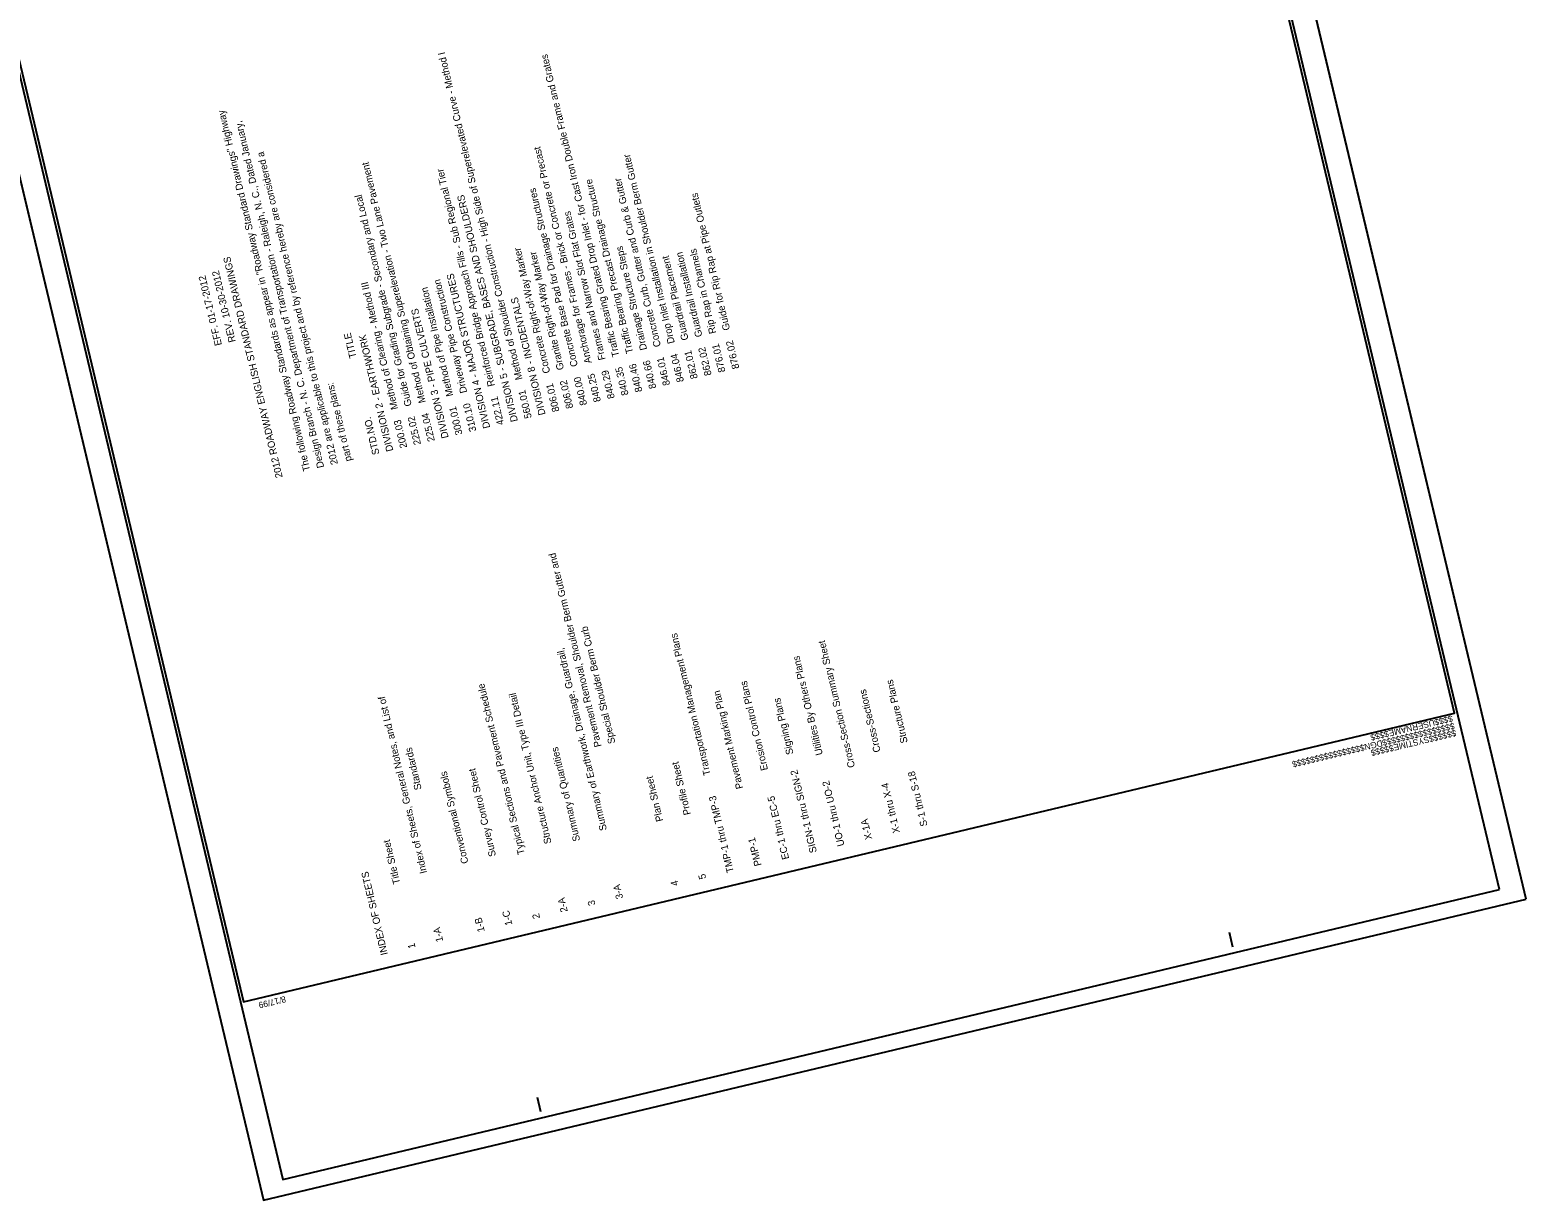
# Model space of a CAD drawing. Extents: x 1734738 to 1742883, y 698103 to 703125.
# Drawn here: x 1740359 to 1742883, y 699342 to 701316 of the extents above; entities that cross this region are included whole.
import ezdxf

# ---------------------------------------------------------------- set-up
doc = ezdxf.new("R2010")
doc.units = 0
for name, color, linetype in [('Default', 7, 'Continuous'), ('Exist Road Primary US Structure Standard Bridge Number Label', 7, 'Continuous'), ('Exist Road Secondary Structure Pipe Number Label', 7, 'Continuous'), ('Exist Road Secondary Type 41 SR Number Label', 7, 'Continuous'), ('Exist Road Secondary Type 51 Number Label', 7, 'Continuous'), ('Map Preparation County Base Positioning Point', 7, 'Continuous')]:
    doc.layers.add(name, color=color, linetype=linetype)

msp = doc.modelspace()

# ---------------------------------------------------------------- linework, layer by layer
at = {"layer": 'Exist Road Primary US Structure Standard Bridge Number Label'}
for p, q in [((1742882.7, 699849.5), (1742102.1, 703124.7)), ((1739971.8, 702617), (1740752.4, 699341.7)), ((1740752.4, 699341.7), (1742882.7, 699849.5))]:
    msp.add_line(p, q, dxfattribs=at)
at = {"layer": 'Exist Road Secondary Structure Pipe Number Label'}
msp.add_lwpolyline([(1742837.8, 699865.5), (1742065.3, 703106.7), (1740012.8, 702617.5), (1740785.3, 699376.3)], close=True, dxfattribs=at)
at = {"layer": 'Exist Road Secondary Type 41 SR Number Label'}
msp.add_lwpolyline([(1742882.7, 699849.5), (1742102.1, 703124.7), (1739971.8, 702617), (1740752.4, 699341.7)], close=True, dxfattribs=at)
at = {"layer": 'Map Preparation County Base Positioning Point'}
for p, q in [((1742761.7, 700163), (1742761.7, 700163)), ((1742388, 699768.6), (1742382.2, 699792.9)), ((1740719, 699676.1), (1740719, 699676.1)), ((1741220.7, 699490.4), (1741214.9, 699514.7))]:
    msp.add_line(p, q, dxfattribs=at)
msp.add_lwpolyline([(1740023.4, 702594.3), (1740719, 699676.1), (1742761.7, 700163), (1742066.2, 703081.2)], close=True, dxfattribs=at)

# ---------------------------------------------------------------- texts
at = {"layer": 'Default'}
for s, p in [('560.01    Method of Shoulder Construction - High Side of Superelevated Curve - Method I', (1741205.3, 700661.8)), ('840.35    Traffic Bearing Grated Drop Inlet - for Cast Iron Double Frame and Grates', (1741368.7, 700700.7)), ('The following Roadway Standards as appear in "Roadway Standard Drawings" Highway', (1740831.7, 700572.8)), ('Design Branch - N. C. Department of Transportation - Raleigh, N. C., Dated January,', (1740855.1, 700578.3)), ('2012 are applicable to this project and by reference hereby are considered a ', (1740878.4, 700583.9)), ('840.25    Anchorage for Frames - Brick or Concrete or Precast', (1741322, 700689.6)), ('846.04    Drop Inlet Installation in Shoulder Berm Gutter', (1741462.1, 700723)), ('225.04    Method of Obtaining Superelevation - Two Lane Pavement', (1741041.9, 700622.8)), ('422.11    Reinforced Bridge Approach Fills - Sub Regional Tier', (1741158.6, 700650.7)), ('840.46    Traffic Bearing Precast Drainage Structure', (1741392, 700706.3)), ('846.01    Concrete Curb, Gutter and Curb & Gutter', (1741438.7, 700717.4)), ('225.02    Guide for Grading Subgrade - Secondary and Local', (1741018.5, 700617.3)), ('DIVISION 5 - SUBGRADE, BASES AND SHOULDERS', (1741181.9, 700656.2)), ('840.00    Concrete Base Pad for Drainage Structures', (1741298.7, 700684)), ('876.02    Guide for Rip Rap at Pipe Outlets', (1741555.5, 700745.3)), ('840.29    Frames and Narrow Slot Flat Grates', (1741345.4, 700695.2)), ('2012 ROADWAY ENGLISH STANDARD DRAWINGS', (1740785.1, 700561.6)), ('806.01    Concrete Right-of-Way Marker', (1741252, 700672.9)), ('806.02    Granite Right-of-Way Marker', (1741275.3, 700678.5)), ('840.66    Drainage Structure Steps', (1741415.4, 700711.9)), ('862.01    Guardrail Placement', (1741485.4, 700728.6)), ('862.02    Guardrail Installation', (1741508.8, 700734.1)), ('876.01    Rip Rap in Channels', (1741532.1, 700739.7)), ('                                                      EFF. 01-17-2012', (1740738.4, 700550.5)), ('                                                      REV. 10-30-2012', (1740761.7, 700556.1)), ('DIVISION 4 - MAJOR STRUCTURES', (1741135.2, 700645.1)), ('200.03    Method of Clearing - Method III', (1740995.2, 700611.7)), ('300.01    Method of Pipe Installation ', (1741088.5, 700634)), ('310.10    Driveway Pipe Construction', (1741111.9, 700639.5)), ('DIVISION 8 - INCIDENTALS', (1741228.6, 700667.4)), ('DIVISION 3 - PIPE CULVERTS', (1741065.2, 700628.4)), ('STD.NO.                       TITLE', (1740948.5, 700600.6)), ('DIVISION 2 - EARTHWORK', (1740971.8, 700606.1)), ('part of these plans:', (1740901.8, 700589.4))]:
    msp.add_text(s, height=12, rotation=103.4059, dxfattribs=at).set_placement(p)
at = {"layer": 'Exist Road Secondary Type 51 Number Label'}
for s, p in [('    Pavement Removal, Shoulder Berm Gutter and', (1741327.2, 700090.1)), ('    Special Shoulder Berm Curb', (1741350.5, 700095.7)), ('TMP-1 thru TMP-3        Transportation Management Plans', (1741546.2, 699895.6)), ('3-A                     Summary of Earthwork, Drainage, Guardrail,', (1741359.5, 699851.1)), ('X-1A                    Cross-Section Summary Sheet', (1741779.7, 699951.2)), ('UO-1 thru UO-2          Utilities By Others Plans', (1741733, 699940.1)), ('S-1 thru S-18           Structure Plans', (1741873.1, 699973.5)), ('2                       Typical Sections and Pavement Schedule', (1741219.4, 699817.7)), ('2-A                     Structure Anchor Unit, Type III Detail', (1741266.1, 699828.8)), ('PMP-1                   Pavement Marking Plan', (1741592.9, 699906.7)), ('EC-1 thru EC-5          Erosion Control Plans', (1741639.6, 699917.8)), ('X-1 thru X-4            Cross-Sections', (1741826.4, 699962.4)), ('1-A                     Index of Sheets, General Notes, and List of', (1741056, 699778.7)), ('SIGN-1 thru SIGN-2      Signing Plans', (1741686.3, 699929)), ('    Standards', (1741023.7, 700017.8)), ('3                       Summary of Quantities', (1741312.8, 699839.9)), ('1-C                     Survey Control Sheet', (1741172.7, 699806.5)), ('5                       Profile Sheet', (1741499.6, 699884.4)), ('1-B                     Conventional Symbols', (1741126, 699795.4)), ('4                       Plan Sheet', (1741452.9, 699873.3)), ('1                       Title Sheet', (1741009.3, 699767.6)), ('INDEX OF SHEETS', (1740962.6, 699756.5))]:
    msp.add_text(s, height=12, rotation=103.4059, dxfattribs=at).set_placement(p)
at = {"layer": 'Map Preparation County Base Positioning Point'}
for s, p in [('$$$$$$$$$$$$$$$$DGN$$$$$$$$$$$$$$$$', (1742760.7, 700147)), ('$$$$USERNAME$$$$', (1742757.6, 700159.8)), ('$$$$$$SYSTIME$$$$$', (1742763.5, 700135.2)), ('8/17/99', (1740789, 699686.1))]:
    msp.add_text(s, height=10.5, rotation=193.4059, dxfattribs=at).set_placement(p)

doc.saveas('drawing.dxf')
